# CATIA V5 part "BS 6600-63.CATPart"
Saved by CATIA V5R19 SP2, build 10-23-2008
Part number: BS 6600-63
Bounding box of the stored display mesh (mm): x -59.975 to 59.975, y -59.975 to 59.975, z 0 to 201
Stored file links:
  C:\Users\Bora\Desktop\3D Katı model\BS serisi\BS 6600\BS 6600-63.CATPart
  C:\Program Files\Dassault Systemes\B19\intel_a\reffiles\standard\MetricThickPitch.txt
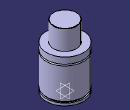
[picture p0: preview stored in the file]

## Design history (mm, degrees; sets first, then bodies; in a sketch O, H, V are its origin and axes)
Body1 (main body)
  Sketch1 on yz-plane, origin (0, 0, 0), H (0, 1, 0), V (0, 0, 1)
    point P1 (60, 117)
    point P2 (60, 112)
    point P3 (60, 117)
    point P7 (37.5, 200)
    point P9 (37.5, 200)
    point P14 (60, 112)
    arc A1 centre (60, 114.5) radius 2.5 from (60, 117) to (60, 112) ccw
    line L1 (60, 117) -> (60, 137)
    line L2 (60, 0) -> (60, 8)
    arc A2 centre (36.5, 200) radius 1 from (37.5, 200) to (36.5, 201) ccw
    line L3 (37.5, 200) -> (37.5, 137)
    line L4 (56, 13) -> (56, 8)
    line L5 (60, 13) -> (60, 112)
    line L6 (36.5, 201) -> (0, 201)
    point P15 (0, 201)
    line L7 (37.5, 137) -> (60, 137)
    line L8 (0, 0) -> (60, 0)
    line L9 (56, 13) -> (60, 13)
    line L10 (56, 8) -> (60, 8)
    coincidence: P15 V, P1 P3, P2 P14, P7 P9
    tangency: L6 A2
    horizontal: L7 H, L8 H, L9 H, L10 H
  Shaft1: profile Sketch1, axis Sketch1.V, angle 360
  Sketch2 on face of Shaft1 from Sketch1.L8, origin (0, 0, 0), H (1, 0, 0), V (0, -1, 0)
    point P1 (40, 0)
    distance P1 V = 40
  Hole1: placed by Sketch2, at (40, 0, 0) direction (0, 0, 1), diameter 8.376, depth 8, threaded "M10", thread diameter 10, thread depth 8, pitch 1.5
  CircPattern1: of Hole1, instances 4, angular step 90, axis from xy-plane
